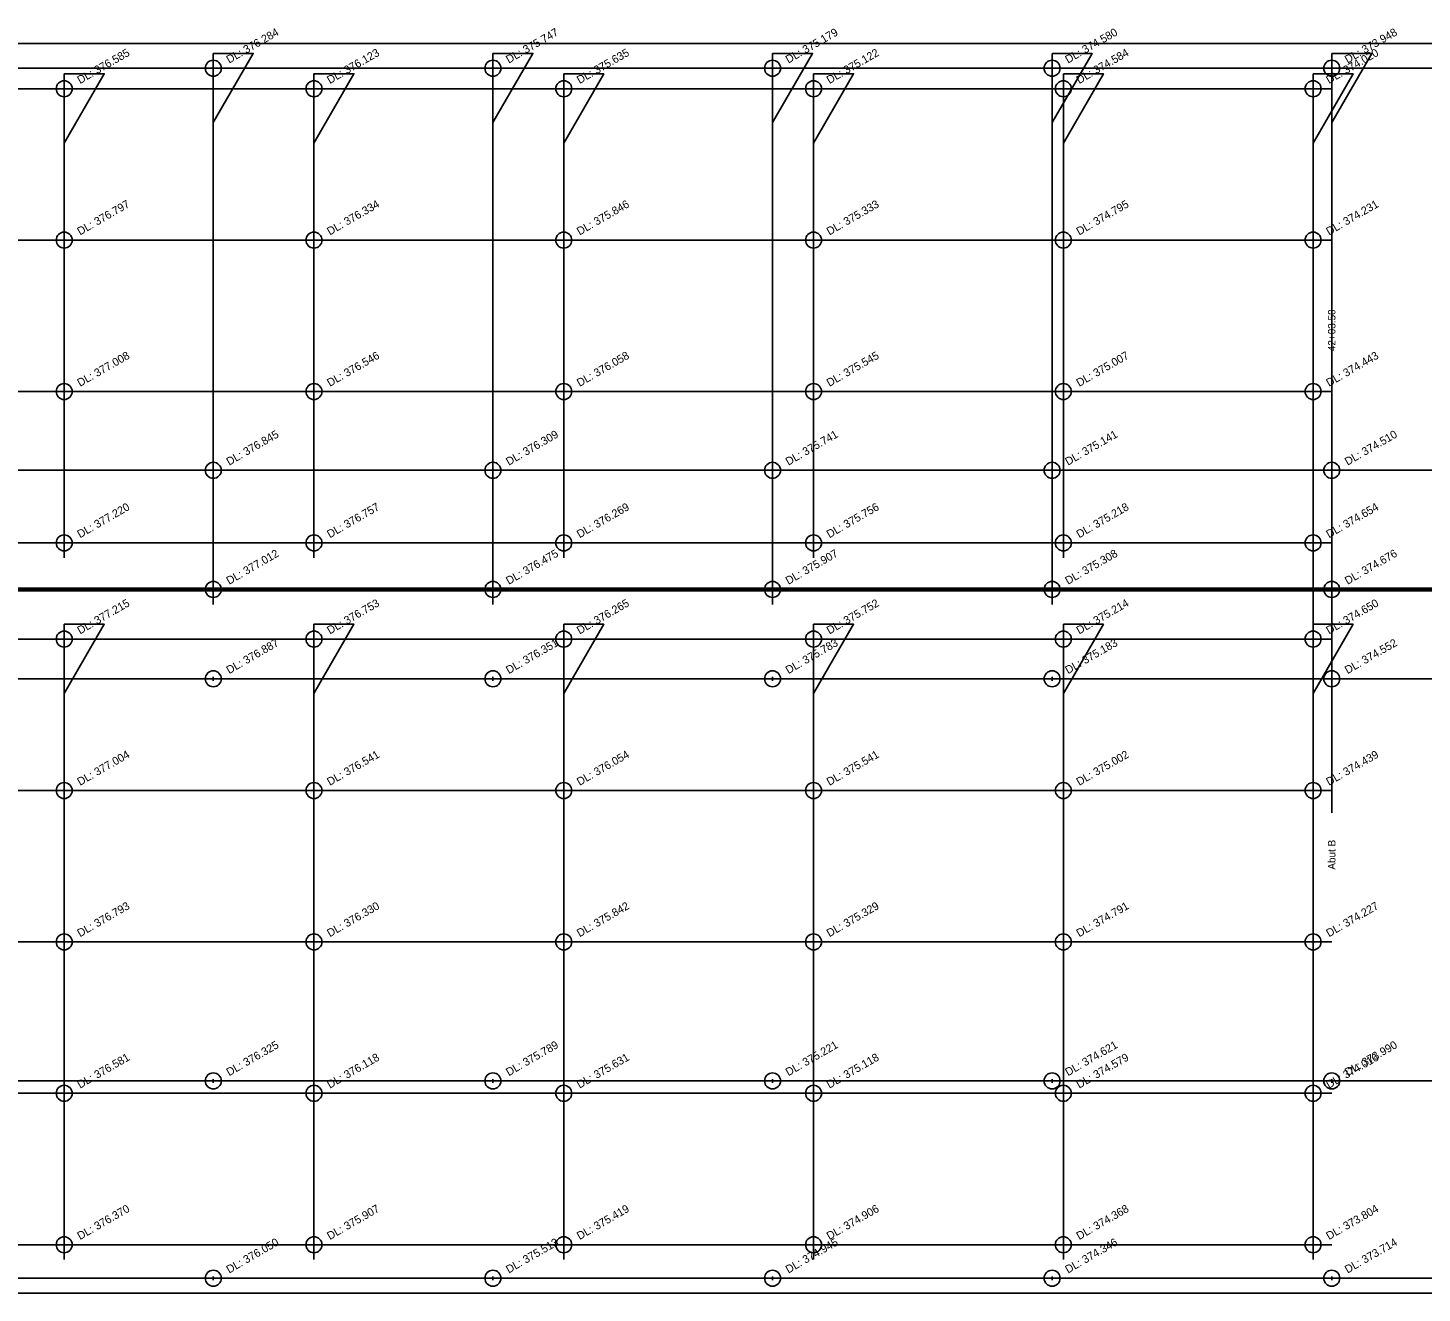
# Model space of a CAD drawing. Extents: x 100440 to 101111, y 50226 to 50315.
# Drawn here: x 100946.9 to 101040.6, y 50225.9 to 50310.9 of the extents above; entities that cross this region are included whole.
import ezdxf

# ---------------------------------------------------------------- set-up
doc = ezdxf.new("R2010")
doc.units = 0
for name, color, linetype in [('Level 1', 7, 'Continuous'), ('Level 10', 7, 'Continuous'), ('Level 21', 7, 'Continuous'), ('Level 23', 7, 'Continuous')]:
    doc.layers.add(name, color=color, linetype=linetype)

msp = doc.modelspace()

# ---------------------------------------------------------------- linework, layer by layer
at = {"layer": 'Level 1'}
for p, q in [((100559.504, 50306.768), (101034.504, 50306.768)), ((100559.504, 50296.601), (101034.504, 50296.601)), ((101033.254, 50288.143), (101033.254, 50258.143)), ((101033.254, 50288.143), (101033.254, 50258.143)), ((100559.504, 50286.435), (101034.504, 50286.435)), ((100559.504, 50276.268), (101034.504, 50276.268)), ((100559.504, 50269.81), (101034.504, 50269.81)), ((100559.504, 50259.643), (101034.504, 50259.643)), ((100559.504, 50249.476), (101034.504, 50249.476)), ((100559.504, 50239.31), (101034.504, 50239.31)), ((100559.504, 50229.143), (101034.504, 50229.143))]:
    msp.add_line(p, q, dxfattribs=at)
at = {"layer": 'Level 10'}
for p, q in [((100959.393, 50273.268), (100959.393, 50273.018)), ((100978.171, 50273.268), (100978.171, 50273.018)), ((100996.949, 50273.268), (100996.949, 50273.018)), ((101015.726, 50273.268), (101015.726, 50273.018)), ((101034.504, 50273.268), (101034.504, 50273.018)), ((100959.393, 50267.268), (100959.393, 50267.018)), ((100978.171, 50267.268), (100978.171, 50267.018)), ((100996.949, 50267.268), (100996.949, 50267.018)), ((101015.726, 50267.268), (101015.726, 50267.018)), ((101034.504, 50267.268), (101034.504, 50267.018)), ((100959.393, 50240.268), (100959.393, 50240.018)), ((100978.171, 50240.268), (100978.171, 50240.018)), ((100996.949, 50240.268), (100996.949, 50240.018)), ((101015.726, 50240.268), (101015.726, 50240.018)), ((101034.504, 50240.268), (101034.504, 50240.018)), ((100959.393, 50227.018), (100959.393, 50226.768)), ((100978.171, 50227.018), (100978.171, 50226.768)), ((100996.949, 50227.018), (100996.949, 50226.768)), ((101015.726, 50227.018), (101015.726, 50226.768)), ((101034.504, 50227.018), (101034.504, 50226.768))]:
    msp.add_line(p, q, dxfattribs=at)
for points in [[(100959.393, 50309.143), (100959.393, 50272.143)], [(100959.393, 50304.489), (100962.08, 50309.143), (100959.393, 50309.143)], [(100978.171, 50309.143), (100978.171, 50272.143)], [(100978.171, 50304.489), (100980.857, 50309.143), (100978.171, 50309.143)], [(100996.949, 50309.143), (100996.949, 50272.143)], [(100996.949, 50304.489), (100999.635, 50309.143), (100996.949, 50309.143)], [(101015.726, 50309.143), (101015.726, 50272.143)], [(101015.726, 50304.489), (101018.413, 50309.143), (101015.726, 50309.143)], [(101034.504, 50309.143), (101034.504, 50272.143)], [(101034.504, 50304.489), (101037.191, 50309.143), (101034.504, 50309.143)], [(100949.379, 50307.768), (100949.379, 50275.268)], [(100949.379, 50303.114), (100952.066, 50307.768), (100949.379, 50307.768)], [(100966.154, 50307.768), (100966.154, 50275.268)], [(100966.154, 50303.114), (100968.841, 50307.768), (100966.154, 50307.768)], [(100982.929, 50307.768), (100982.929, 50275.268)], [(100982.929, 50303.114), (100985.616, 50307.768), (100982.929, 50307.768)], [(100999.704, 50307.768), (100999.704, 50275.268)], [(100999.704, 50303.114), (101002.391, 50307.768), (100999.704, 50307.768)], [(101016.479, 50307.768), (101016.479, 50275.268)], [(101016.479, 50303.114), (101019.166, 50307.768), (101016.479, 50307.768)], [(101033.254, 50307.768), (101033.254, 50275.268)], [(101033.254, 50303.114), (101035.941, 50307.768), (101033.254, 50307.768)], [(100949.379, 50270.81), (100949.379, 50228.143)], [(100949.379, 50266.156), (100952.066, 50270.81), (100949.379, 50270.81)], [(100966.154, 50270.81), (100966.154, 50228.143)], [(100966.154, 50266.156), (100968.841, 50270.81), (100966.154, 50270.81)], [(100982.929, 50270.81), (100982.929, 50228.143)], [(100982.929, 50266.156), (100985.616, 50270.81), (100982.929, 50270.81)], [(100999.704, 50270.81), (100999.704, 50228.143)], [(100999.704, 50266.156), (101002.391, 50270.81), (100999.704, 50270.81)], [(101016.479, 50270.81), (101016.479, 50228.143)], [(101016.479, 50266.156), (101019.166, 50270.81), (101016.479, 50270.81)], [(101033.254, 50270.81), (101033.254, 50228.143)], [(101033.254, 50266.156), (101035.941, 50270.81), (101033.254, 50270.81)]]:
    msp.add_lwpolyline(points, dxfattribs=at)
for centre in [(100959.393, 50308.143), (100978.171, 50308.143), (100996.949, 50308.143), (101015.726, 50308.143), (101034.504, 50308.143), (100949.379, 50306.768), (100966.154, 50306.768), (100982.929, 50306.768), (100999.704, 50306.768), (101016.479, 50306.768), (101033.254, 50306.768), (100949.379, 50296.601), (100966.154, 50296.601), (100982.929, 50296.601), (100999.704, 50296.601), (101016.479, 50296.601), (101033.254, 50296.601), (100949.379, 50286.435), (100966.154, 50286.435), (100982.929, 50286.435), (100999.704, 50286.435), (101016.479, 50286.435), (101033.254, 50286.435), (100959.393, 50281.143), (100978.171, 50281.143), (100996.949, 50281.143), (101015.726, 50281.143), (101034.504, 50281.143), (100949.379, 50276.268), (100966.154, 50276.268), (100982.929, 50276.268), (100999.704, 50276.268), (101016.479, 50276.268), (101033.254, 50276.268), (100959.393, 50273.143), (100959.393, 50273.143), (100978.171, 50273.143), (100978.171, 50273.143), (100996.949, 50273.143), (100996.949, 50273.143), (101015.726, 50273.143), (101015.726, 50273.143), (101034.504, 50273.143), (101034.504, 50273.143), (100949.379, 50269.81), (100966.154, 50269.81), (100982.929, 50269.81), (100999.704, 50269.81), (101016.479, 50269.81), (101033.254, 50269.81), (100959.393, 50267.143), (100978.171, 50267.143), (100996.949, 50267.143), (101015.726, 50267.143), (101034.504, 50267.143), (100949.379, 50259.643), (100966.154, 50259.643), (100982.929, 50259.643), (100999.704, 50259.643), (101016.479, 50259.643), (101033.254, 50259.643), (100949.379, 50249.476), (100966.154, 50249.476), (100982.929, 50249.476), (100999.704, 50249.476), (101016.479, 50249.476), (101033.254, 50249.476), (100949.379, 50239.31), (100959.393, 50240.143), (100966.154, 50239.31), (100978.171, 50240.143), (100982.929, 50239.31), (100996.949, 50240.143), (100999.704, 50239.31), (101015.726, 50240.143), (101016.479, 50239.31), (101033.254, 50239.31), (101034.504, 50240.143), (100949.379, 50229.143), (100966.154, 50229.143), (100982.929, 50229.143), (100999.704, 50229.143), (101016.479, 50229.143), (101033.254, 50229.143), (100959.393, 50226.893), (100978.171, 50226.893), (100996.949, 50226.893), (101015.726, 50226.893), (101034.504, 50226.893)]:
    msp.add_circle(centre, 0.537, dxfattribs=at)
at = {"layer": 'Level 23'}
for p, q in [((100439.554, 50309.81), (101111.484, 50309.81)), ((100439.554, 50308.143), (101111.484, 50308.143)), ((101034.504, 50288.143), (101034.504, 50258.143)), ((101034.504, 50288.143), (101034.504, 50258.143)), ((100439.554, 50281.143), (101111.484, 50281.143)), ((100439.554, 50273.226), (101111.484, 50273.226)), ((100439.554, 50273.143), (101111.484, 50273.143)), ((100448.204, 50273.143), (101107.514, 50273.143)), ((100448.204, 50273.06), (101107.514, 50273.06)), ((100448.204, 50267.143), (101107.514, 50267.143)), ((100448.204, 50240.143), (101107.514, 50240.143)), ((100448.204, 50226.893), (101107.514, 50226.893)), ((100448.204, 50225.893), (101107.514, 50225.893))]:
    msp.add_line(p, q, dxfattribs=at)

# ---------------------------------------------------------------- texts
at = {"layer": 'Level 10'}
for s, p in [('DL: 376.284', (100960.458, 50308.448)), ('DL: 375.747', (100979.236, 50308.448)), ('DL: 375.179', (100998.014, 50308.448)), ('DL: 374.580', (101016.791, 50308.448)), ('DL: 373.948', (101035.569, 50308.448)), ('DL: 376.585', (100950.444, 50307.073)), ('DL: 376.123', (100967.219, 50307.073)), ('DL: 375.635', (100983.994, 50307.073)), ('DL: 375.122', (101000.769, 50307.073)), ('DL: 374.584', (101017.544, 50307.073)), ('DL: 374.020', (101034.319, 50307.073)), ('DL: 376.797', (100950.444, 50296.906)), ('DL: 376.334', (100967.219, 50296.906)), ('DL: 375.846', (100983.994, 50296.906)), ('DL: 375.333', (101000.769, 50296.906)), ('DL: 374.795', (101017.544, 50296.906)), ('DL: 374.231', (101034.319, 50296.906)), ('DL: 377.008', (100950.444, 50286.739)), ('DL: 376.546', (100967.219, 50286.739)), ('DL: 376.058', (100983.994, 50286.739)), ('DL: 375.545', (101000.769, 50286.739)), ('DL: 375.007', (101017.544, 50286.739)), ('DL: 374.443', (101034.319, 50286.739)), ('DL: 376.845', (100960.458, 50281.448)), ('DL: 376.309', (100979.236, 50281.448)), ('DL: 374.510', (101035.569, 50281.448)), ('DL: 375.741', (100998.014, 50281.448)), ('DL: 375.141', (101016.791, 50281.448)), ('DL: 377.220', (100950.444, 50276.573)), ('DL: 376.757', (100967.219, 50276.573)), ('DL: 376.269', (100983.994, 50276.573)), ('DL: 375.756', (101000.769, 50276.573)), ('DL: 375.218', (101017.544, 50276.573)), ('DL: 374.654', (101034.319, 50276.573)), ('DL: 377.012', (100960.458, 50273.448)), ('DL: 377.012', (100960.458, 50273.448)), ('DL: 376.475', (100979.236, 50273.448)), ('DL: 376.475', (100979.236, 50273.448)), ('DL: 375.907', (100998.014, 50273.448)), ('DL: 375.907', (100998.014, 50273.448)), ('DL: 375.308', (101016.791, 50273.448)), ('DL: 375.308', (101016.791, 50273.448)), ('DL: 374.676', (101035.569, 50273.448)), ('DL: 374.676', (101035.569, 50273.448)), ('DL: 377.215', (100950.444, 50270.114)), ('DL: 376.753', (100967.219, 50270.114)), ('DL: 376.265', (100983.994, 50270.114)), ('DL: 375.752', (101000.769, 50270.114)), ('DL: 375.214', (101017.544, 50270.114)), ('DL: 374.650', (101034.319, 50270.114)), ('DL: 376.887', (100960.458, 50267.448)), ('DL: 376.351', (100979.236, 50267.448)), ('DL: 375.783', (100998.014, 50267.448)), ('DL: 375.183', (101016.791, 50267.448)), ('DL: 374.552', (101035.569, 50267.448)), ('DL: 377.004', (100950.444, 50259.948)), ('DL: 376.541', (100967.219, 50259.948)), ('DL: 376.054', (100983.994, 50259.948)), ('DL: 375.541', (101000.769, 50259.948)), ('DL: 375.002', (101017.544, 50259.948)), ('DL: 374.439', (101034.319, 50259.948)), ('DL: 376.793', (100950.444, 50249.781)), ('DL: 376.330', (100967.219, 50249.781)), ('DL: 375.842', (100983.994, 50249.781)), ('DL: 375.329', (101000.769, 50249.781)), ('DL: 374.791', (101017.544, 50249.781)), ('DL: 374.227', (101034.319, 50249.781)), ('DL: 376.325', (100960.458, 50240.448)), ('DL: 375.789', (100979.236, 50240.448)), ('DL: 375.221', (100998.014, 50240.448)), ('DL: 374.621', (101016.791, 50240.448)), ('DL: 373.990', (101035.569, 50240.448)), ('DL: 376.581', (100950.444, 50239.614)), ('DL: 376.118', (100967.219, 50239.614)), ('DL: 375.631', (100983.994, 50239.614)), ('DL: 375.118', (101000.769, 50239.614)), ('DL: 374.579', (101017.544, 50239.614)), ('DL: 374.016', (101034.319, 50239.614)), ('DL: 376.370', (100950.444, 50229.448)), ('DL: 375.907', (100967.219, 50229.448)), ('DL: 375.419', (100983.994, 50229.448)), ('DL: 374.906', (101000.769, 50229.448)), ('DL: 374.368', (101017.544, 50229.448)), ('DL: 373.804', (101034.319, 50229.448)), ('DL: 376.050', (100960.458, 50227.198)), ('DL: 375.513', (100979.236, 50227.198)), ('DL: 374.945', (100998.014, 50227.198)), ('DL: 374.346', (101016.791, 50227.198)), ('DL: 373.714', (101035.569, 50227.198))]:
    msp.add_text(s, height=0.53732, rotation=30, dxfattribs=at).set_placement(p)
at = {"layer": 'Level 21'}
for s, p in [('42+03.50', (101034.754, 50289.143)), ('42+03.50', (101034.754, 50289.143)), ('Abut B', (101034.754, 50254.328)), ('Abut B', (101034.754, 50254.328))]:
    msp.add_text(s, height=0.5, rotation=90, dxfattribs=at).set_placement(p)

doc.saveas('drawing.dxf')
